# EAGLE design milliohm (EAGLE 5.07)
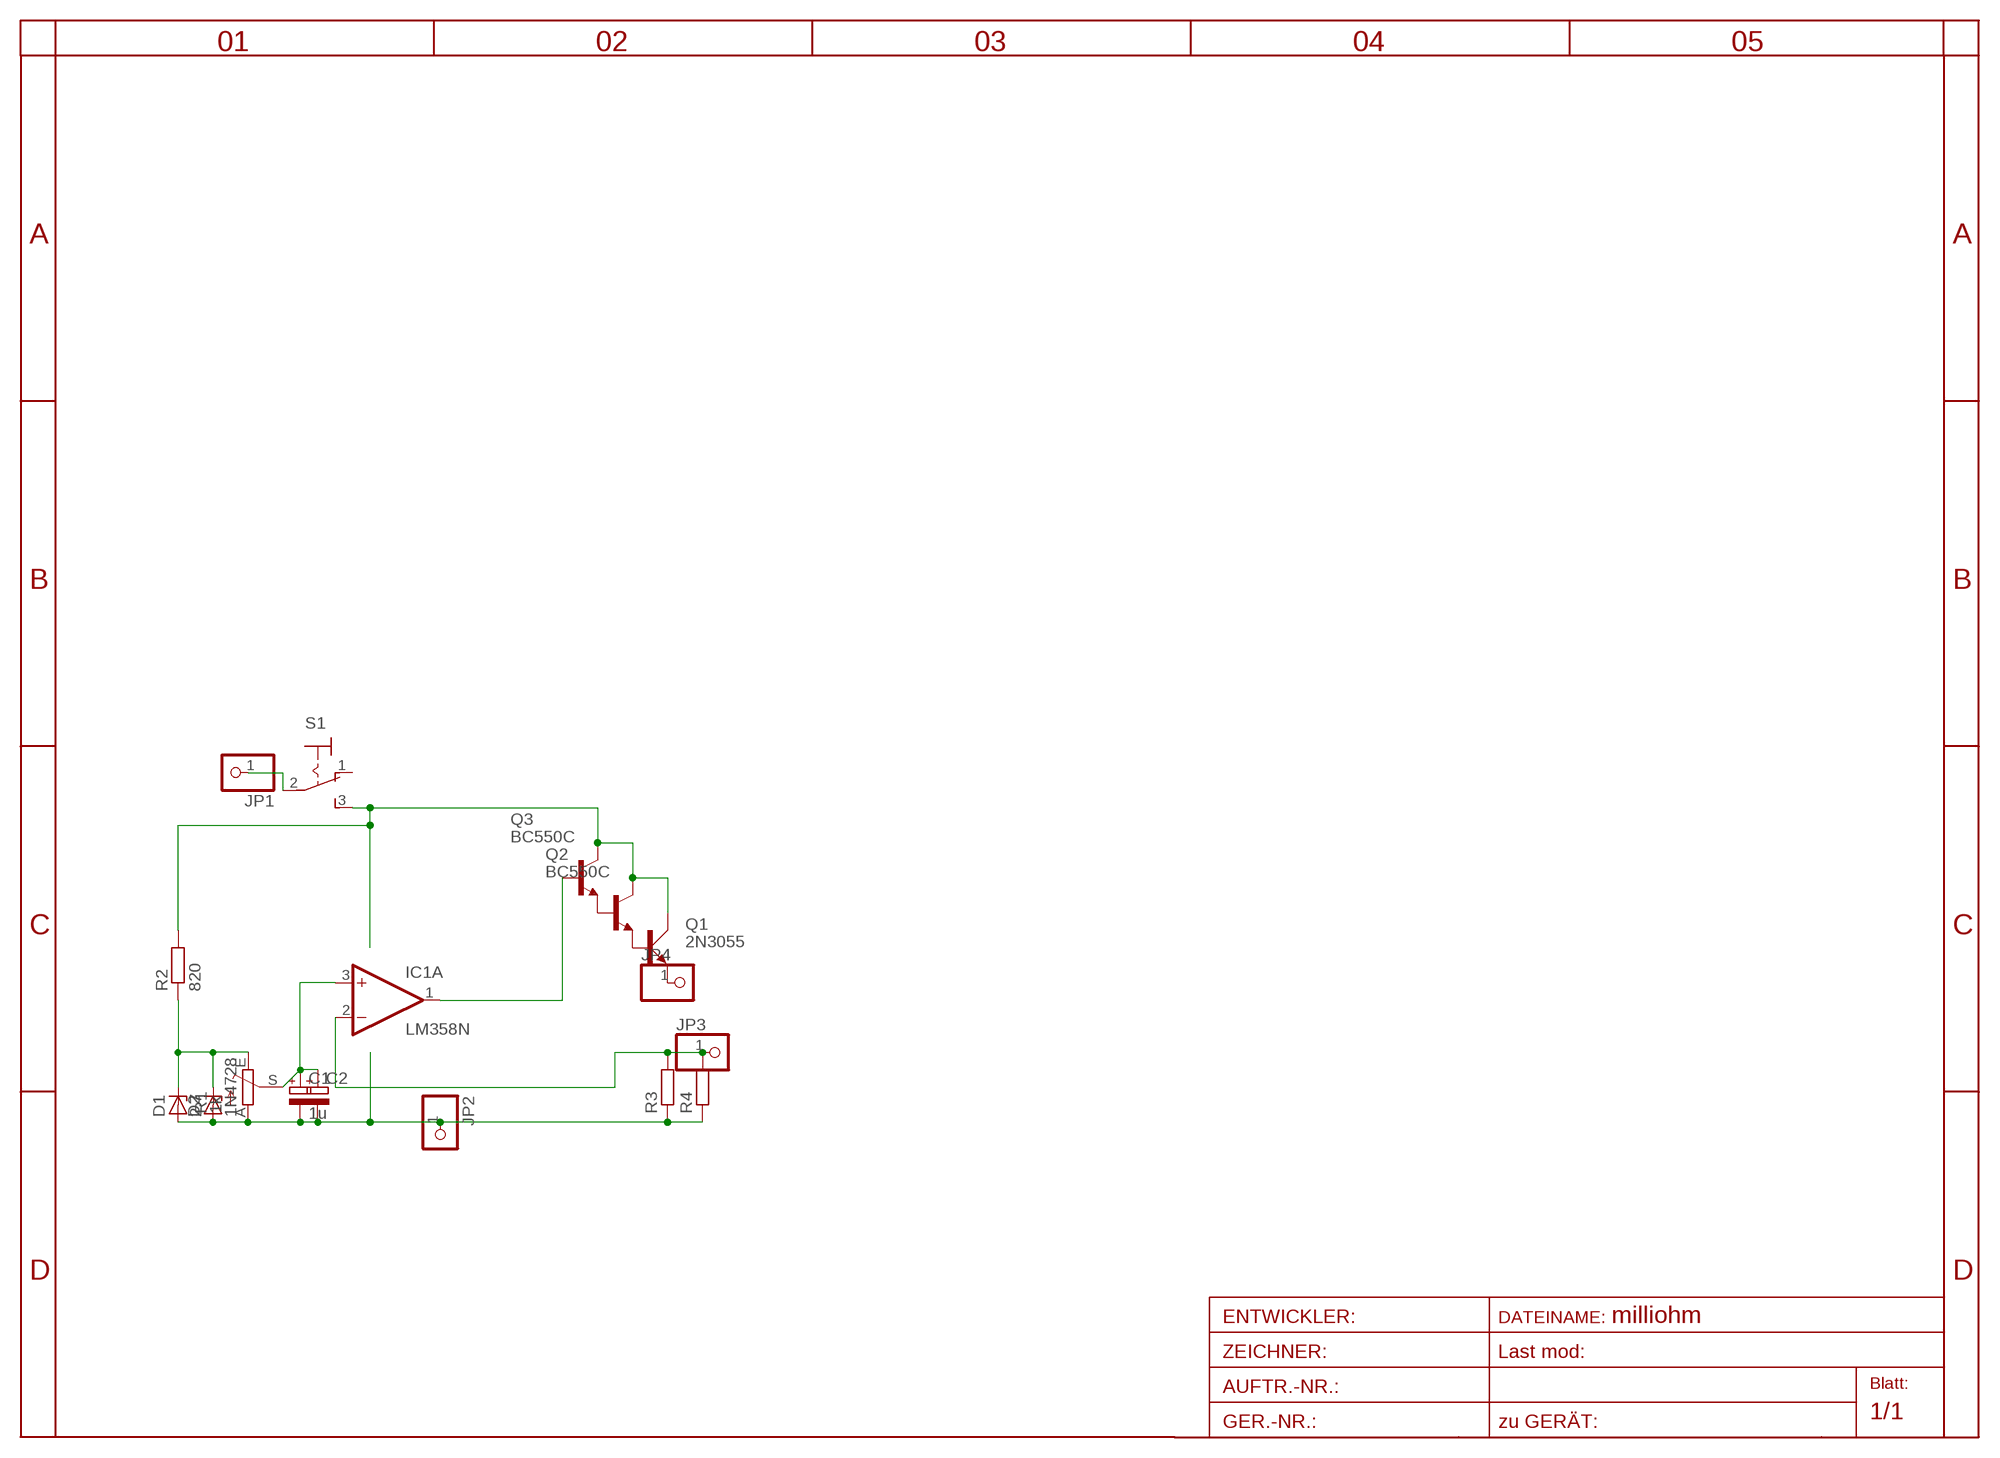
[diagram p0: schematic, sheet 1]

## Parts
C1  1u  CPOL-EU140CLH-0810  [140CLH-0810]
C2  CPOL-EUE5-5  [E5-5]
D1  2.7  ZENER-DIODESOT23  [SOT23]
D2  1N4728  [DO41Z10]
IC1  LM358N  [DIL08]
JP1  PINHD-1X1  [1X01]
JP2  PINHD-1X1  [1X01]
JP3  PINHD-1X1  [1X01]
JP4  PINHD-1X1  [1X01]
Q1  2N3055  [TO3A]
Q2  BC550C  [TO92-EBC]
Q3  BC550C  [TO92-EBC]
R1  1k  TRIM_EU-CA9V  [CA9V]
R2  820  R-EU_0207/10  [0207/10]
R3  R-EU_0207/10  [0207/10]
R4  R-EU_0207/10  [0207/10]
S1  320-916  [320-916]

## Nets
N$1: Q1.B Q2.E
N$2: Q2.B Q3.E
N$3: C1.+ C2.+ IC1.3(A:+IN) R1.S
N$4: D1.3(C) D2.C R1.E R2.1
N$6: IC1.1(A:OUT) Q3.B
N$8: IC1.2(A:-IN) JP3.1 R3.2 R4.2
N$9: JP4.1 Q1.E
N$10: JP1.1 S1.2(P)
V+: Q1.C1(C) Q2.C Q3.C R2.2 S1.3(S)
V-: C1.- C2.- D1.1(A) D2.A JP2.1 R1.A R3.1 R4.1
Unconnected: IC1.5(B:+IN) IC1.6(B:-IN) IC1.7(B:OUT) Q1.C S1.1(O)

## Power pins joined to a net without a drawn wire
V+: IC1.8(P:V+)
V-: IC1.4(P:V-)

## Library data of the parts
C1 C2 = rcl-2:CPOL-EU: POLARIZED CAPACITOR, European symbol
D1 = diode:ZENER-DIODE: Z-Diode
D2 = diode-1:1N4728: Z DIODE
IC1 = linear:LM358: OP AMP also LM158; LM258; LM2904 Source: http://cache.national.com/ds/LM/LM158.pdf
JP1-JP4 = pinhead:PINHD-1X1: PIN HEADER
Q1 = transistor-power:2N3055: NPN TRANSISTOR
Q2 Q3 = transistor-npn:BC550*: NPN Transistor
R1 = pot:TRIM_EU-: POTENTIOMETER
R2-R4 = rcl-2:R-EU_: RESISTOR, European symbol
S1 = switch:320-916: TOGGLE SWITCH distributor RS Components

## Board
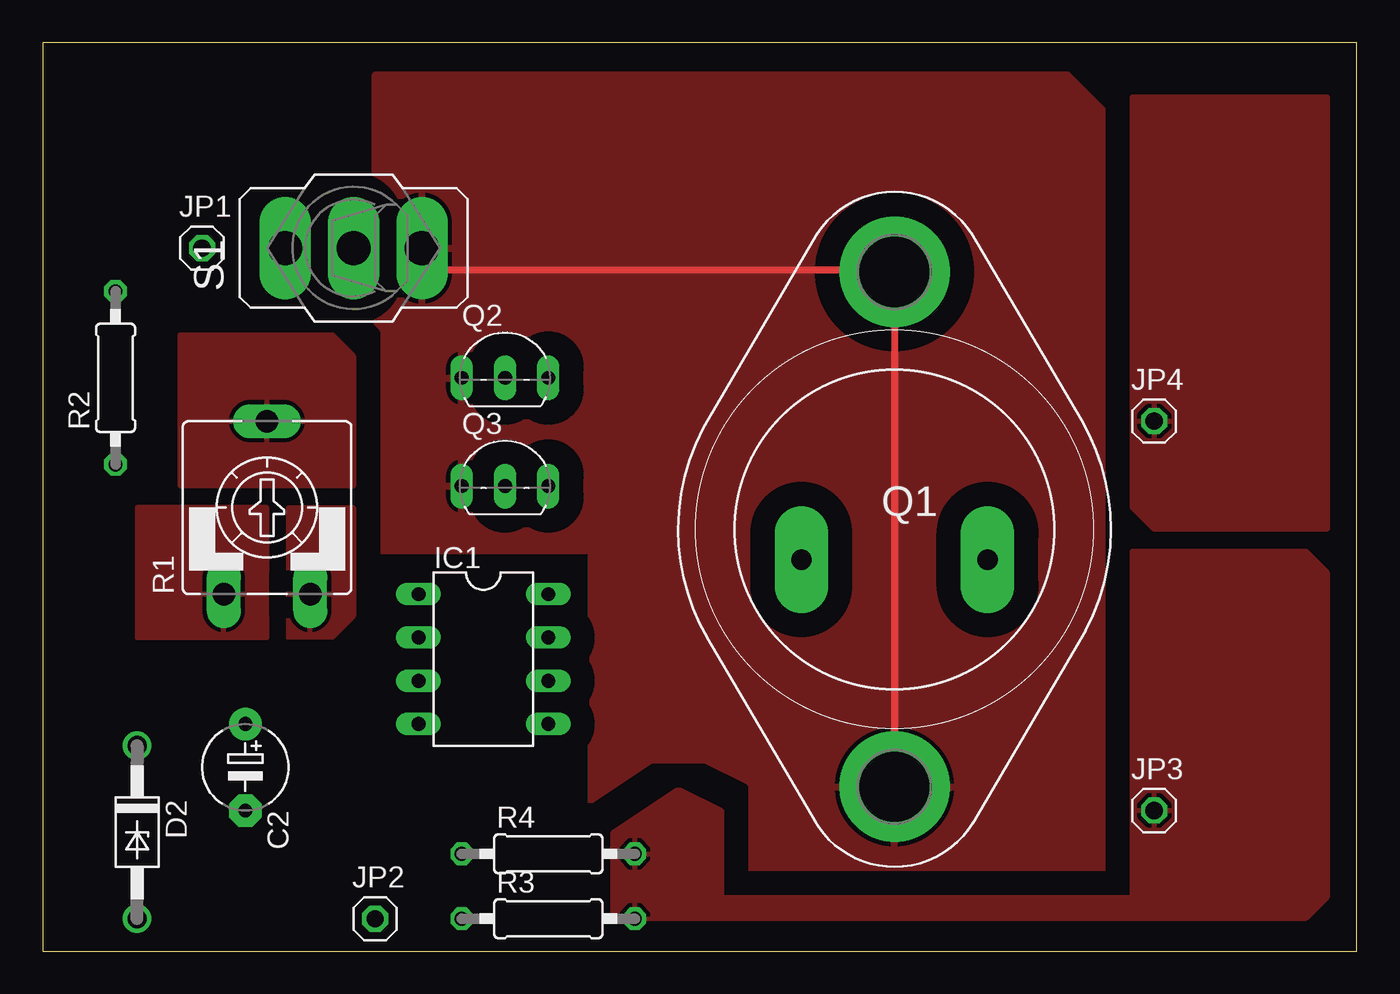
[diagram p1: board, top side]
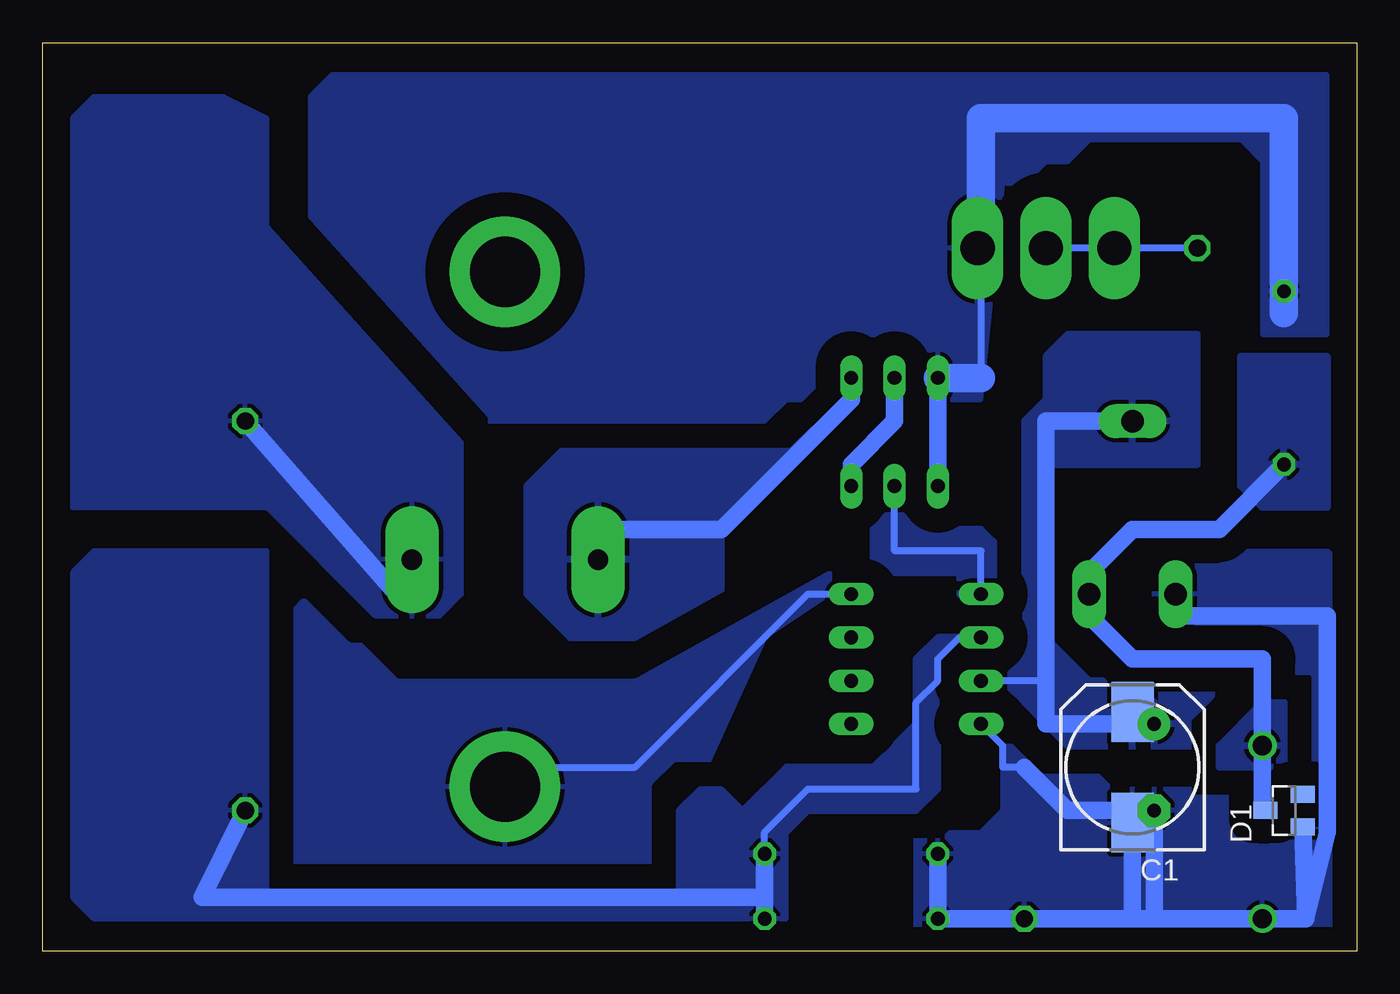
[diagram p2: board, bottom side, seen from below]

Size 77.14 x 53.33 mm. Coordinates in mm from the lower left corner, seen from the top.
Outline: 0,0 77.14,0 77.14,53.33 0,53.33 0,0
Copper layers (1*16): Top 0.035mm / dielectric 1.5mm / Bottom 0.035mm
Design rules "default": minimum track width 40mil, minimum drill 24mil, track to track 8mil, track to pad 8mil, pad to pad 8mil, via to via 8mil, smd to smd 8mil, copper to edge 40mil, drill to drill 8mil, minimum pad ring 10mil, minimum via ring 8mil, stop-mask expansion 4mil, vias tented up to drill 0mil, thermal gap 10mil

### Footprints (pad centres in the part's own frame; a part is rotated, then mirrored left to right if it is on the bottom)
140CLH-0810 = smd 3.5 x 2.5: + 3.25,0; - -3.25,0
E5-5 = drill 0.813 pad 1.905 round: + -2.54,0 | drill 0.813 pad 1.905 octagon: - 2.54,0
SOT23 = smd 1 x 1.4: 1 -0.95,-1.1; 2 0.95,-1.1; 3 0,1.1
DO41Z10 = drill 1.118 round: A 5.08,0; C -5.08,0
DIL08 = drill 0.813 long: 1 -3.81,-3.81; 2 -1.27,-3.81; 3 1.27,-3.81; 4 3.81,-3.81; 5 3.81,3.81; 6 1.27,3.81; 7 -1.27,3.81; 8 -3.81,3.81
1X01 = drill 1.016 octagon: 1 0,0
TO3A = drill 1.194 pad 3.15 long: B -1.778,5.461; E -1.778,-5.461 | drill 4.115 pad 6.477 round: C 15.113,0; C1 -15.113,0
TO92-EBC = drill 0.813 long: B 0,-1.27; C -2.54,-1.27; E 2.54,-1.27
CA9V = drill 1.321 long: A -2.54,-5.08; E 2.54,-5.08; S 0,5.08
0207/10 = drill 0.813 octagon: 1 -5.08,0; 2 5.08,0
320-916 = drill 2.007 long: 1 0,4.013; 2 0,0; 3 0,-4.013

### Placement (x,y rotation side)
C1  13.17,10.79 90 bottom
C2  11.9,10.79 270 top
D1  4.28,8.25 90 bottom
D2  5.55,6.98 270 top
IC1  25.87,17.14 270 top
JP1  9.36,41.27 0 top
JP2  19.52,1.9 0 top
JP3  65.24,8.25 0 top
JP4  65.24,31.11 0 top
Q1  50,24.76 90 top
Q2  27.14,34.92 0 top
Q3  27.14,28.57 0 top
R1  13.17,26.03 0 top
R2  4.28,33.65 90 top
R3  29.68,1.9 0 top
R4  29.68,5.71 0 top
S1  18.25,41.27 90 top

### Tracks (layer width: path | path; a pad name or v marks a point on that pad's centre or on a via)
N$1
  Bottom 1.016: Q2.E 29.68,32.38 37.3,24.76 43.65,24.76 Q1.B
  pour Bottom (isolate 1.422, rank 3): 30.95,34.92 30.95,32.38 32.22,31.11 44.92,31.11 48.73,27.3 48.73,20.95 46.19,18.41 39.84,18.41 37.3,20.95 37.3,24.76 29.68,32.38 29.68,36.19
N$2
  Bottom 1.016: Q3.E 29.68,28.57 27.14,31.11 Q2.B
N$3
  Bottom 0.406: 18.25,15.87 IC1.3
  Bottom 1.016: 13.17,13.33 18.25,13.33 18.25,15.87 18.25,31.11 R1.S | C2.+ 13.17,13.33 | 13.17,13.33 C1.+
  pour Top (isolate 1.422): 18.25,27.3 8.09,27.3 8.09,36.19 16.98,36.19 18.25,34.92
  pour Bottom (isolate 1.422, rank 2): 6.82,15.87 15.71,15.87 18.25,18.41 18.25,28.57 9.36,28.57 9.36,36.19 16.98,36.19 18.25,34.92 18.25,32.38 19.52,31.11 19.52,17.14 20.79,15.87 16.98,12.06 9.36,12.06 8.09,13.33
N$4
  Bottom 1.016: D1.3 5.55,8.25 D2.C 5.55,17.14 13.17,17.14 15.71,19.68 R1.E 15.71,22.22 13.17,24.76 8.09,24.76 R2.1
  pour Top (isolate 1.422): 14.44,26.03 18.25,26.03 18.25,20.95 18.25,19.68 16.98,18.41 14.44,18.41
  pour Bottom (isolate 1.422): 4.28,14.6 4.28,10.79 8.09,10.79 8.09,12.06 5.55,14.6
  pour Bottom (isolate 1.422, rank 2): 1.74,34.92 1.74,26.03 5.55,26.03 6.82,27.3 6.82,34.92
N$6
  Bottom 0.406: IC1.1 22.06,23.49 27.14,23.49 Q3.B
  pour Bottom (isolate 1.422, rank 3): 20.79,20.95 20.79,23.49 22.06,24.76 25.87,24.76 27.14,26.03 28.41,24.76 28.41,22.22 23.33,22.22 23.33,20.95
N$8
  Bottom 0.406: IC1.2 23.33,18.41 24.6,17.14 24.6,15.87 25.87,14.6 25.87,9.52 32.22,9.52 34.76,6.98 R4.2
  Bottom 1.016: R3.2 34.76,3.17 | 34.76,3.17 R4.2 | JP3.1 67.78,3.17 34.76,3.17
  pour Top (isolate 1.422): 63.97,23.49 74.13,23.49 75.4,22.22 75.4,3.17 74.13,1.9 33.49,1.9 33.49,6.98 37.3,9.52 39.84,8.25 39.84,3.17 63.97,3.17
  pour Bottom (isolate 1.422): 33.49,6.98 34.76,6.98 37.3,9.52 38.57,9.52 39.84,8.25 39.84,3.17 63.97,3.17 63.97,23.49 74.13,23.49 75.4,22.22 75.4,3.17 74.13,1.9 33.49,1.9
  pour Bottom (isolate 1.422, rank 2): 23.33,18.41 24.6,18.41 25.87,17.14 25.87,13.33 28.41,10.79 33.49,10.79 36.03,8.25 36.03,5.71 34.76,5.71 32.22,8.25 25.87,8.25 24.6,9.52 24.6,17.14
N$9
  Bottom 1.016: JP4.1 56.35,20.95 Q1.E
  pour Bottom (isolate 1.422): 52.54,20.95 52.54,29.84 63.97,42.54 63.97,48.89 66.51,50.16 74.13,50.16 75.4,48.89 75.4,26.03 63.97,26.03 57.62,19.68 53.81,19.68
  pour Top (isolate 1.422): 63.97,50.16 75.4,50.16 75.4,24.76 65.24,24.76 63.97,26.03
N$10
  Bottom 0.406: JP1.1 S1.2
V+  (via drill 0.6)
  Top 0.406: v50,10.79 50,40 22.06,40 22.06,41.27 S1.3 | v50,10.79 Q1.C1 | Q1.C1 50,9.52 | v50,10.79 Q1.C1
  Bottom 0.406: S1.3 22.06,41.27 22.06,33.65 | 4.28,37.46 4.28,40 | IC1.8 32.22,20.95 42.38,10.79 v50,10.79
  Bottom 1.016: 4.28,40 R2.2 | Q2.C Q3.C
  Bottom 1.676: 22.06,33.65 Q2.C | 22.06,41.27 22.06,48.89 4.28,48.89 4.28,37.46
  pour Top (isolate 1.422, rank 2): 19.52,51.43 60.16,51.43 62.7,48.89 62.7,3.17 60.16,0.63 32.22,0.63 32.22,23.49 19.52,23.49
  pour Bottom (isolate 1.422, rank 2): 62.7,4.44 62.7,19.68 61.43,20.95 56.35,15.87 42.38,15.87 30.95,22.22 30.95,20.95 34.76,18.41 41.11,4.44
  pour Bottom (isolate 1.422, rank 2): 1.74,51.43 60.16,51.43 61.43,50.16 61.43,41.27 51.27,31.11 34.76,31.11 33.49,32.38 22.06,32.38 20.79,45.08 19.52,45.08 18.25,46.35 16.98,46.35 15.71,47.62 6.82,47.62 5.55,46.35 5.55,36.19 1.74,36.19
V-
  Bottom 0.406: 19.52,10.79 20.79,10.79 20.79,12.06 IC1.4
  Bottom 1.016: R4.1 R3.1 JP2.1 13.17,1.9 | 3.01,1.9 D2.A 11.9,1.9 | 11.9,1.9 13.17,1.9 | 19.52,10.79 16.98,8.25 13.17,8.25 C1.- 13.17,1.9 | 3.01,1.9 1.74,6.98 1.74,19.68 10.63,19.68 R1.A | 3.01,1.9 D1.1 | 11.9,1.9 C2.-
  pour Top (isolate 1.422): 13.17,18.41 13.17,26.03 5.55,26.03 5.55,18.41
  pour Bottom (isolate 1.422, rank 3): 25.87,0.63 25.87,6.98 22.06,6.98 20.79,8.25 20.79,12.06 16.98,12.06 14.44,9.52 8.09,9.52 5.55,6.98 4.28,6.98 4.28,18.41 11.9,18.41 11.9,22.22 10.63,23.49 1.74,23.49 0.47,22.22 0.47,1.9 1.74,0.63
